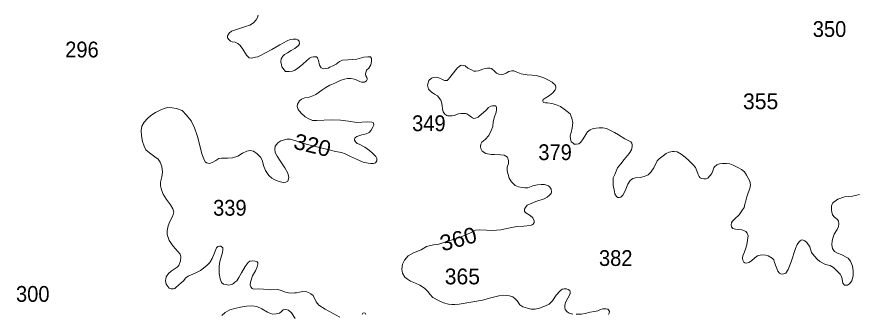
# Model space of a CAD drawing. Extents: x 445.4 to 500, y 8728.7 to 8784.
# Drawn here: x 486.23 to 494.73, y 8734.54 to 8737.55 of the extents above; entities that cross this region are included whole.
import ezdxf
from ezdxf.enums import TextEntityAlignment as Align

# ---------------------------------------------------------------- set-up
doc = ezdxf.new("R2010")
doc.units = 0
doc.header["$LTSCALE"] = 0.064
doc.layers.add('2', color=7, linetype='Continuous', lineweight=13)
doc.layers.add('21', color=7, linetype='Continuous')
doc.layers.add('61', color=7, linetype='Continuous')

msp = doc.modelspace()

# ---------------------------------------------------------------- linework, layer by layer
at = {"layer": '2'}
for points in [[(488.3782, 8737.3877), (488.4047, 8737.4076), (488.4644, 8737.4308), (488.544, 8737.4573), (488.5904, 8737.4705), (488.6268, 8737.4931), (488.6534, 8737.5229), (488.6666, 8737.5477), (488.6733, 8737.5726)], [(489.0788, 8736.6162), (489.07, 8736.6459), (489.0718, 8736.6687), (489.0928, 8736.7019), (489.1121, 8736.7211), (489.1454, 8736.7334), (489.1892, 8736.7404), (489.226, 8736.7544), (489.2575, 8736.7666), (489.3173, 8736.8097), (489.3576, 8736.8377), (489.3996, 8736.8622), (489.4487, 8736.8831), (489.5048, 8736.9094), (489.5486, 8736.9234), (489.5784, 8736.9286), (489.6134, 8736.9304), (489.6484, 8736.9234), (489.7028, 8736.8989), (489.7203, 8736.8919), (489.7518, 8736.8936), (489.7693, 8736.9041), (489.7763, 8736.9181), (489.7763, 8736.9286), (489.7746, 8736.9409), (489.7623, 8736.9566), (489.7606, 8736.9723), (489.7623, 8736.9898), (489.7711, 8737.0143), (489.7956, 8737.0353), (489.8149, 8737.0668), (489.8219, 8737.1), (489.8202, 8737.1315), (489.8114, 8737.1472), (489.7834, 8737.149), (489.7448, 8737.1455), (489.673, 8737.1262), (489.5836, 8737.1192), (489.5293, 8737.114), (489.4985, 8737.1008), (489.4637, 8737.076), (489.4305, 8737.0561), (489.4007, 8737.0429), (489.3841, 8737.0329), (489.3592, 8737.0296), (489.3393, 8737.028), (489.3277, 8737.0296), (489.3128, 8737.0379), (489.2962, 8737.066), (489.2846, 8737.1107), (489.2747, 8737.1372), (489.2631, 8737.1488), (489.2531, 8737.1504), (489.2349, 8737.1504), (489.215, 8737.1471), (489.1918, 8737.1355), (489.1619, 8737.1091), (489.1254, 8737.0743), (489.089, 8737.0429), (489.0608, 8737.0247), (489.0458, 8737.0147), (489.021, 8737.0031), (488.9878, 8736.9998), (488.9513, 8737.0015), (488.9364, 8737.0164), (488.9128, 8737.048), (488.9094, 8737.0662), (488.9028, 8737.0977), (488.9078, 8737.1275), (488.9227, 8737.154), (488.9409, 8737.1738), (488.9691, 8737.1904), (489.0089, 8737.2119), (489.0454, 8737.2334), (489.0835, 8737.2648), (489.0918, 8737.2814), (489.0885, 8737.3079), (489.0769, 8737.3228), (489.057, 8737.3277), (489.0288, 8737.3294), (488.999, 8737.3261), (488.9675, 8737.3112), (488.8945, 8737.2715), (488.8116, 8737.2235), (488.7486, 8737.1904), (488.6988, 8737.1639), (488.669, 8737.1473), (488.6474, 8737.144), (488.6076, 8737.1341), (488.5811, 8737.1391), (488.5562, 8737.1655), (488.5198, 8737.2251), (488.4909, 8737.2636), (488.466, 8737.2851), (488.4395, 8737.2967), (488.4113, 8737.3017), (488.3931, 8737.3066), (488.3748, 8737.3232), (488.3616, 8737.3431), (488.3632, 8737.3629), (488.3782, 8737.3877)], [(491.1262, 8736.1565), (491.0675, 8736.1582), (491.0348, 8736.1599), (490.9778, 8736.1702), (490.9416, 8736.1943), (490.9278, 8736.2185), (490.9244, 8736.2391), (490.9295, 8736.2632), (490.9399, 8736.2839), (490.9709, 8736.3114), (491.0089, 8736.3527), (491.0348, 8736.401), (491.0486, 8736.4415), (491.0538, 8736.4914), (491.0659, 8736.5414), (491.0831, 8736.5879), (491.0883, 8736.612), (491.0883, 8736.6343), (491.0797, 8736.6516), (491.0641, 8736.6533), (491.0469, 8736.6533), (491.0296, 8736.6481), (491.0072, 8736.6361), (490.9779, 8736.6033), (490.9348, 8736.5689), (490.9089, 8736.5431), (490.9003, 8736.5379), (490.8899, 8736.5328), (490.8744, 8736.5259), (490.8589, 8736.5241), (490.8451, 8736.5293), (490.833, 8736.5379), (490.8071, 8736.5569), (490.7881, 8736.5724), (490.7726, 8736.5758), (490.7519, 8736.5741), (490.7295, 8736.5741), (490.7036, 8736.5724), (490.6829, 8736.5655), (490.6622, 8736.5551), (490.6381, 8736.55), (490.6225, 8736.55), (490.5949, 8736.5517), (490.5829, 8736.5551), (490.5656, 8736.5672), (490.5484, 8736.5913), (490.5397, 8736.6206), (490.5363, 8736.655), (490.5311, 8736.6894), (490.5242, 8736.7101), (490.4897, 8736.7531), (490.458, 8736.7711), (490.4269, 8736.7934), (490.3993, 8736.821), (490.389, 8736.8623), (490.401, 8736.9088), (490.4286, 8736.9329), (490.4493, 8736.9398), (490.47, 8736.9432), (490.5045, 8736.9363), (490.5459, 8736.9157), (490.5597, 8736.9088), (490.5891, 8736.9088), (490.5994, 8736.9208), (490.6149, 8736.9381), (490.6756, 8737.0166), (490.6928, 8737.039), (490.7084, 8737.0511), (490.7222, 8737.0597), (490.7377, 8737.0631), (490.7687, 8737.0562), (490.7981, 8737.0356), (490.8326, 8737.0183), (490.8584, 8737.0028), (490.8774, 8737.0046), (490.9033, 8737.008), (490.9481, 8737.0235), (490.974, 8737.0304), (490.9947, 8737.0338), (491.0189, 8737.0338), (491.0378, 8737.0304), (491.0672, 8737.0028), (491.0879, 8736.9822), (491.112, 8736.9719), (491.1345, 8736.9684), (491.1621, 8736.9719), (491.1862, 8736.9822), (491.1966, 8736.9891), (491.2138, 8736.9994), (491.2431, 8737.008), (491.2638, 8737.008), (491.288, 8736.9977), (491.3354, 8736.9769), (491.3975, 8736.9666), (491.4493, 8736.9631), (491.4889, 8736.9597), (491.5269, 8736.9511), (491.5683, 8736.9373), (491.608, 8736.9166), (491.6494, 8736.8908), (491.6649, 8736.8788)], [(491.6649, 8736.8788), (491.6752, 8736.8702), (491.6839, 8736.8581), (491.6873, 8736.8426), (491.6873, 8736.8288), (491.6804, 8736.8133), (491.6563, 8736.7841), (491.6252, 8736.7565), (491.5786, 8736.7298), (491.5614, 8736.716), (491.5562, 8736.7074), (491.5562, 8736.6988), (491.5648, 8736.6867), (491.5821, 8736.6816), (491.6028, 8736.6816), (491.6476, 8736.6747), (491.6856, 8736.6643), (491.7339, 8736.6454), (491.7735, 8736.6196), (491.8029, 8736.5955), (491.8322, 8736.5696), (491.8494, 8736.5283), (491.8598, 8736.4784), (491.8551, 8736.4279), (491.843, 8736.3831), (491.8344, 8736.347), (491.8379, 8736.3194), (491.843, 8736.2884), (491.8587, 8736.2758), (491.8743, 8736.2638), (491.8967, 8736.2621), (491.9226, 8736.2672), (491.9415, 8736.2844), (491.964, 8736.3171), (491.9933, 8736.3602), (492.0105, 8736.3877), (492.0347, 8736.4084), (492.0675, 8736.4222), (492.0968, 8736.4273), (492.1261, 8736.4291), (492.1658, 8736.4291), (492.2003, 8736.4222), (492.2365, 8736.4067), (492.2814, 8736.3809), (492.3228, 8736.3585), (492.3883, 8736.3171), (492.4271, 8736.2964), (492.4478, 8736.2861), (492.4564, 8736.2723), (492.4599, 8736.2568), (492.4599, 8736.2413), (492.453, 8736.2052), (492.4306, 8736.169), (492.3805, 8736.1087), (492.3452, 8736.0659), (492.3116, 8736.0233), (492.2841, 8735.9562), (492.2689, 8735.9212), (492.2674, 8735.8846), (492.2674, 8735.8435), (492.2797, 8735.8017), (492.2873, 8735.759), (492.3011, 8735.7331), (492.3148, 8735.724), (492.3286, 8735.7225), (492.3469, 8735.727), (492.3667, 8735.7484), (492.3896, 8735.7895), (492.4171, 8735.8566), (492.4415, 8735.8962), (492.4675, 8735.9145), (492.4934, 8735.9221), (492.5408, 8735.9251), (492.582, 8735.9343), (492.6247, 8735.9541), (492.6507, 8735.9785), (492.6812, 8736.0227), (492.7139, 8736.0935), (492.7352, 8736.1134), (492.7765, 8736.1438), (492.807, 8736.1682), (492.8375, 8736.1834), (492.8696, 8736.1895), (492.8879, 8736.1895), (492.9184, 8736.185), (492.9566, 8736.1636), (492.9978, 8736.1332), (493.039, 8736.0935), (493.0803, 8736.0539), (493.1032, 8736.0265), (493.1169, 8735.993), (493.1306, 8735.9564), (493.1413, 8735.9351), (493.1505, 8735.9214), (493.1627, 8735.9153), (493.1871, 8735.9107), (493.2116, 8735.9107), (493.2283, 8735.9198), (493.2467, 8735.9427), (493.2665, 8735.9656), (493.2818, 8736.0036)], [(487.5188, 8736.4858), (487.5541, 8736.5253), (487.5856, 8736.5551), (487.6329, 8736.5848), (487.689, 8736.611), (487.7328, 8736.6302), (487.7573, 8736.6337), (487.8011, 8736.632), (487.8467, 8736.6268), (487.9027, 8736.6058), (487.9465, 8736.5585), (487.9939, 8736.5008), (488.0289, 8736.4309), (488.0604, 8736.3417), (488.0727, 8736.2892), (488.1028, 8736.1657), (488.122, 8736.1149), (488.136, 8736.0852), (488.1501, 8736.0747), (488.1623, 8736.0695), (488.1834, 8736.0677), (488.2149, 8736.08), (488.2447, 8736.0992), (488.2762, 8736.1184), (488.3025, 8736.1219), (488.3638, 8736.1202), (488.4146, 8736.1237), (488.4672, 8736.1412), (488.5163, 8736.1726), (488.5583, 8736.1919), (488.5924, 8736.2005), (488.6274, 8736.1918), (488.6642, 8736.1655), (488.701, 8736.1271), (488.7185, 8736.0921), (488.7273, 8736.0484), (488.7466, 8735.9959), (488.7799, 8735.9469), (488.8132, 8735.9207), (488.8412, 8735.9032), (488.885, 8735.884), (488.9256, 8735.8767), (488.9554, 8735.8784), (488.9747, 8735.8872), (488.9852, 8735.9256), (488.9729, 8735.9711), (488.9431, 8736.0236), (488.8958, 8736.0935), (488.8643, 8736.1408), (488.845, 8736.1792), (488.8433, 8736.2142), (488.845, 8736.2439), (488.8731, 8736.2772), (488.9046, 8736.2964), (488.9624, 8736.3139), (488.9975, 8736.3139), (489.0535, 8736.2964), (489.1611, 8736.2651), (489.3082, 8736.2267), (489.3801, 8736.2092), (489.4572, 8736.1882), (489.5167, 8736.1794), (489.5553, 8736.1655), (489.6096, 8736.1392), (489.6709, 8736.1112), (489.7375, 8736.0815), (489.7873, 8736.0717), (489.8136, 8736.0682), (489.8399, 8736.0682), (489.8609, 8736.0752), (489.8766, 8736.0944), (489.8766, 8736.1189), (489.8644, 8736.1381), (489.8311, 8736.1731), (489.8013, 8736.2011), (489.7522, 8736.2343), (489.6962, 8736.264), (489.6752, 8736.271), (489.6594, 8736.2868), (489.6489, 8736.3043), (489.6524, 8736.327), (489.6734, 8736.341), (489.7225, 8736.3567), (489.7663, 8736.369), (489.7978, 8736.3829), (489.8171, 8736.4057), (489.8363, 8736.4354), (489.8434, 8736.4564), (489.8399, 8736.4809), (489.8241, 8736.4861), (489.7768, 8736.4896), (489.6716, 8736.4844), (489.5875, 8736.4966), (489.5087, 8736.5054), (489.4141, 8736.5089), (489.2687, 8736.5019), (489.2231, 8736.5019), (489.1857, 8736.52), (489.1489, 8736.541), (489.1103, 8736.5777), (489.0788, 8736.6162)], [(488.998, 8734.7528), (488.9507, 8734.7633), (488.9051, 8734.7807), (488.8736, 8734.7895), (488.8, 8734.786), (488.7281, 8734.7947), (488.6721, 8734.7965), (488.6248, 8734.793), (488.6142, 8734.8017), (488.6002, 8734.8192), (488.5915, 8734.835), (488.5943, 8734.8655), (488.6153, 8734.9285), (488.6451, 8734.9809), (488.6644, 8735.0194), (488.6714, 8735.0474), (488.6697, 8735.0614), (488.6627, 8735.0701), (488.6434, 8735.0789), (488.6136, 8735.0806), (488.5908, 8735.0771), (488.5715, 8735.0631), (488.5418, 8735.0229), (488.505, 8734.96), (488.4787, 8734.9127), (488.4577, 8734.8778), (488.4384, 8734.8638), (488.4244, 8734.8498), (488.4138, 8734.8445), (488.4033, 8734.841), (488.3735, 8734.8358), (488.349, 8734.841), (488.321, 8734.8463), (488.3017, 8734.862), (488.2894, 8734.8987), (488.2789, 8734.953), (488.2789, 8735.0264), (488.2859, 8735.0736), (488.3121, 8735.1654), (488.3156, 8735.1934), (488.3156, 8735.2144), (488.2945, 8735.2284), (488.2823, 8735.2284), (488.2665, 8735.2249), (488.2507, 8735.2126), (488.2297, 8735.1637), (488.2087, 8735.106), (488.1842, 8735.064), (488.1526, 8735.0325), (488.0895, 8734.9818), (488.0352, 8734.9569), (487.9634, 8734.9255), (487.9424, 8734.9097), (487.9179, 8734.8782), (487.8713, 8734.8375), (487.8398, 8734.8095), (487.8293, 8734.8008), (487.8153, 8734.799), (487.7925, 8734.7973), (487.7715, 8734.8043), (487.7434, 8734.8445), (487.7364, 8734.8795), (487.7434, 8734.9179), (487.7644, 8734.9512), (487.7925, 8734.9774), (487.824, 8734.9966), (487.8521, 8735.0176), (487.8696, 8735.0334), (487.8853, 8735.0806), (487.8891, 8735.1203), (487.882, 8735.1483), (487.8593, 8735.1762), (487.8137, 8735.2305), (487.7717, 8735.2882), (487.7524, 8735.3476), (487.7524, 8735.3861), (487.7611, 8735.4351), (487.7804, 8735.4805), (487.8085, 8735.5359), (487.819, 8735.5762), (487.8103, 8735.6094), (487.7857, 8735.6479), (487.7454, 8735.7021), (487.7121, 8735.758), (487.6946, 8735.8018), (487.6858, 8735.843), (487.6858, 8735.878), (487.6963, 8735.9322), (487.7033, 8735.9812), (487.6963, 8736.0371), (487.6823, 8736.0808), (487.6612, 8736.1123), (487.6262, 8736.1368), (487.5736, 8736.177), (487.5363, 8736.206), (487.5188, 8736.2427), (487.5013, 8736.2899), (487.4908, 8736.3494), (487.489, 8736.4019), (487.4943, 8736.4456), (487.5188, 8736.4858)], [(491.8294, 8734.7813), (491.8139, 8734.7917), (491.7949, 8734.7968), (491.7742, 8734.7985), (491.7535, 8734.7951), (491.7311, 8734.7779), (491.6932, 8734.7348), (491.6552, 8734.6746), (491.6207, 8734.6419), (491.5845, 8734.6246), (491.5241, 8734.6005), (491.4793, 8734.5902), (491.4379, 8734.5902), (491.4016, 8734.6005), (491.3551, 8734.616), (491.3223, 8734.635), (491.2981, 8734.6746), (491.2774, 8734.697), (491.2533, 8734.7159), (491.2197, 8734.7279), (491.1852, 8734.7313), (491.1472, 8734.7348), (491.111, 8734.7279), (491.0282, 8734.7072), (490.9471, 8734.6831), (490.8488, 8734.6642), (490.7108, 8734.6435), (490.6659, 8734.6384), (490.6349, 8734.6384), (490.6021, 8734.6435), (490.5521, 8734.6556), (490.4986, 8734.6797), (490.4425, 8734.7107), (490.4131, 8734.7417), (490.3959, 8734.7675), (490.3579, 8734.8037), (490.3113, 8734.8347), (490.2682, 8734.8536), (490.2165, 8734.876), (490.1854, 8734.8966), (490.1595, 8734.9173), (490.1337, 8734.9569), (490.1298, 8734.9976), (490.135, 8735.0475), (490.154, 8735.0871), (490.1936, 8735.1302), (490.2471, 8735.1612), (490.323, 8735.1939), (490.3799, 8735.2249), (490.4507, 8735.2438), (490.5041, 8735.249), (490.731, 8735.3255), (490.8242, 8735.3651), (490.8742, 8735.391), (490.9173, 8735.3961), (490.9863, 8735.391), (491.045, 8735.3892), (491.1312, 8735.3944), (491.2089, 8735.4134), (491.2917, 8735.4306), (491.3641, 8735.4323), (491.4271, 8735.4384), (491.4478, 8735.4452), (491.4598, 8735.4521), (491.4685, 8735.4693), (491.4702, 8735.4866), (491.4564, 8735.5176), (491.4271, 8735.5399), (491.3857, 8735.5692), (491.3719, 8735.5813), (491.3719, 8735.6054), (491.3805, 8735.6209), (491.3977, 8735.645), (491.4374, 8735.6639), (491.484, 8735.6828), (491.5685, 8735.7087), (491.5996, 8735.7259), (491.6254, 8735.7465), (491.641, 8735.7638), (491.6427, 8735.7793), (491.641, 8735.8085), (491.6289, 8735.8292), (491.6134, 8735.843), (491.5737, 8735.855), (491.5392, 8735.855), (491.5012, 8735.8516), (491.4564, 8735.8412), (491.4046, 8735.8223), (491.3753, 8735.8206), (491.3477, 8735.824), (491.3098, 8735.8309), (491.277, 8735.8447), (491.2388, 8735.8819), (491.2163, 8735.9198), (491.1956, 8735.9938), (491.1956, 8736.0317), (491.209, 8736.0669), (491.209, 8736.0997), (491.1986, 8736.1306), (491.1641, 8736.153), (491.1262, 8736.1565)], [(493.2818, 8736.0036), (493.2879, 8736.025), (493.2955, 8736.0341), (493.3176, 8736.0553), (493.3466, 8736.0659), (493.3771, 8736.069), (493.4168, 8736.069), (493.4489, 8736.0629), (493.4855, 8736.0507), (493.5328, 8736.0263), (493.568, 8736.0065), (493.5985, 8735.9821), (493.6199, 8735.9501), (493.6367, 8735.9197), (493.6534, 8735.8877), (493.658, 8735.8526), (493.6524, 8735.8151), (493.6371, 8735.7709), (493.6219, 8735.7313), (493.6112, 8735.6902), (493.6035, 8735.6551), (493.5944, 8735.6231), (493.5715, 8735.5881), (493.544, 8735.547), (493.501, 8735.5078), (493.4781, 8735.4835), (493.4659, 8735.4652), (493.4628, 8735.4469), (493.4659, 8735.4271), (493.4811, 8735.4103), (493.4949, 8735.4042), (493.5086, 8735.4012), (493.5361, 8735.3997), (493.5712, 8735.3951), (493.5926, 8735.389), (493.6139, 8735.3799), (493.6262, 8735.3631), (493.6368, 8735.3341), (493.6307, 8735.2915), (493.6231, 8735.2442), (493.6098, 8735.1994), (493.593, 8735.1567), (493.5823, 8735.1323), (493.5792, 8735.1095), (493.5808, 8735.0866), (493.5915, 8735.0683), (493.6037, 8735.0622), (493.6205, 8735.0592), (493.6418, 8735.0638), (493.6693, 8735.0805), (493.7044, 8735.111), (493.7319, 8735.1323), (493.7579, 8735.1384), (493.7869, 8735.1415), (493.8159, 8735.14), (493.8388, 8735.1308), (493.8785, 8735.108), (493.8955, 8735.0923), (493.9038, 8735.0631), (493.9185, 8735.0214), (493.9352, 8734.9755), (493.954, 8734.9567), (493.9728, 8734.9463), (493.9958, 8734.9484), (494.0188, 8734.9547), (494.0396, 8734.9922), (494.0731, 8735.0714), (494.1149, 8735.2049), (494.1337, 8735.2466), (494.1483, 8735.2716), (494.1629, 8735.2841), (494.1713, 8735.2904), (494.1859, 8735.2925), (494.2089, 8735.2841), (494.2298, 8735.2654), (494.259, 8735.2216), (494.2778, 8735.1673), (494.3071, 8735.1277), (494.3342, 8735.0965), (494.3635, 8735.0735), (494.4181, 8735.0441), (494.4678, 8735.0331), (494.5009, 8735.0138), (494.5672, 8734.9448), (494.5838, 8734.9173), (494.5921, 8734.8732), (494.5949, 8734.8539), (494.6115, 8734.8346), (494.6418, 8734.8346), (494.6612, 8734.8483), (494.686, 8734.8787), (494.6999, 8734.9283), (494.6999, 8734.9807), (494.6943, 8735.0276), (494.6722, 8735.0772), (494.6474, 8735.1075), (494.5783, 8735.1461), (494.5396, 8735.1599), (494.5092, 8735.1765), (494.4899, 8735.2068), (494.4844, 8735.2426)], [(494.4844, 8735.2426), (494.4871, 8735.284), (494.4954, 8735.3198), (494.5065, 8735.3502), (494.5369, 8735.3998), (494.5507, 8735.4301), (494.5534, 8735.4549), (494.5507, 8735.4825), (494.5424, 8735.4991), (494.512, 8735.5239), (494.4899, 8735.5487), (494.4788, 8735.5901), (494.4813, 8735.6388), (494.4923, 8735.6692), (494.5448, 8735.705), (494.6111, 8735.7298), (494.6912, 8735.7381), (494.7631, 8735.7519)], [(491.8608, 8734.5395), (491.8246, 8734.5498), (491.8039, 8734.5653), (491.7832, 8734.5894), (491.778, 8734.6084), (491.778, 8734.6273), (491.7846, 8734.6591), (491.8087, 8734.7021), (491.8277, 8734.7331), (491.8346, 8734.7503), (491.8346, 8734.7658), (491.8294, 8734.7813)], [(489.4999, 8734.5093), (489.3509, 8734.5898), (489.2896, 8734.6335), (489.2598, 8734.6667), (489.231, 8734.7283), (489.2082, 8734.7475), (489.1837, 8734.7615), (489.1662, 8734.7685), (489.1259, 8734.7703), (489.0926, 8734.765), (489.061, 8734.758), (489.0418, 8734.7563), (488.998, 8734.7528)], [(488.3068, 8734.5258), (488.3387, 8734.559), (488.3862, 8734.5837), (488.4375, 8734.5989), (488.4946, 8734.6103), (488.5554, 8734.6216), (488.6086, 8734.6254), (488.66, 8734.6178), (488.7094, 8734.5932), (488.7683, 8734.5609), (488.7969, 8734.5476), (488.8216, 8734.54), (488.8558, 8734.5438), (488.8881, 8734.5495), (488.909, 8734.5685), (488.9262, 8734.5837), (488.9547, 8734.5894), (488.9794, 8734.5818), (489.0098, 8734.5533), (489.0497, 8734.4983)], [(489.7645, 8734.5373), (489.7574, 8734.5496), (489.7487, 8734.5531), (489.7329, 8734.5496), (489.7259, 8734.5373)], [(492.2231, 8734.5378), (492.2282, 8734.5498), (492.2317, 8734.5671), (492.2231, 8734.5843), (492.2144, 8734.5929), (492.1937, 8734.5963), (492.1817, 8734.5963), (492.1627, 8734.5963), (492.1403, 8734.5894), (492.1127, 8734.5757), (492.0799, 8734.5688), (492.0368, 8734.5602), (491.9867, 8734.5481), (491.9488, 8734.5412), (491.8953, 8734.5395)]]:
    msp.add_lwpolyline(points, dxfattribs=at)

# ---------------------------------------------------------------- texts
at = {"layer": '21', "width": 0.95}
for s, p in [('350', (494.2904, 8737.3506)), ('296', (486.7194, 8737.143)), ('349', (490.2328, 8736.3957)), ('379', (491.511, 8736.1021)), ('339', (488.2173, 8735.5388)), ('382', (492.1252, 8735.0293)), ('300', (486.2212, 8734.6659))]:
    msp.add_text(s, height=0.16, dxfattribs=at).set_placement(p)
at = {"layer": '21'}
for s, p in [('355', (493.5838, 8736.618)), ('365', (490.563, 8734.8429))]:
    msp.add_text(s, height=0.16, dxfattribs=at).set_placement(p)
at = {"layer": '61', "width": 1.05}
for s, rotation, p in [('320', 346.239, (489.2043, 8736.1762)), ('360', 15.259, (490.721, 8735.2254))]:
    msp.add_text(s, height=0.16, rotation=rotation, dxfattribs=at).set_placement(p, align=Align.CENTER)

doc.saveas('drawing.dxf')
